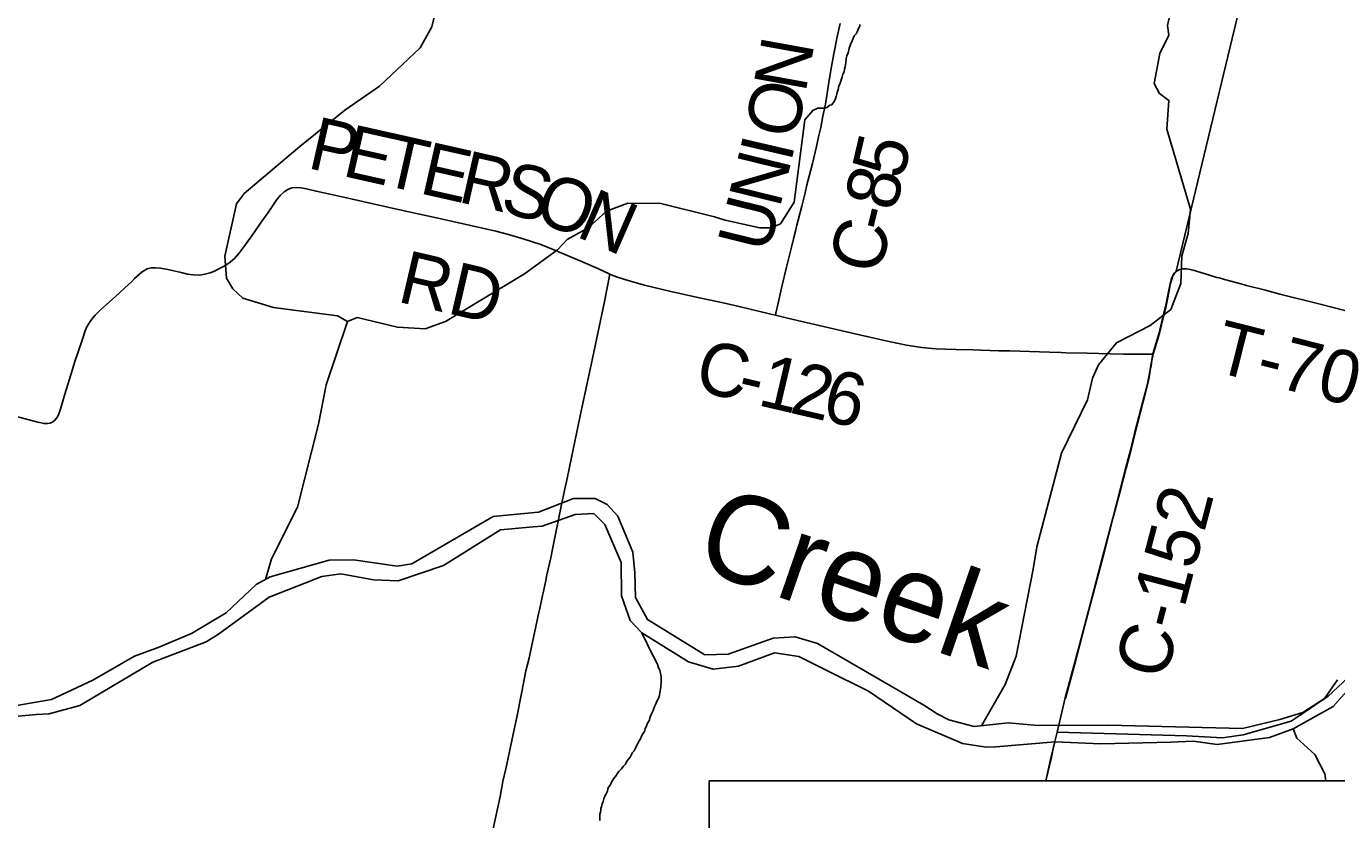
# Model space of a CAD drawing. Extents: x -1.4 to 35.4, y 0 to 22.
# Drawn here: x 12.391 to 13.799, y 14.45 to 15.303 of the extents above; entities that cross this region are included whole.
import ezdxf

# ---------------------------------------------------------------- set-up
doc = ezdxf.new("R2010")
doc.units = 0
for name, color, linetype in [('GM_X_County_Road', 7, 'Continuous'), ('GM_X_County_Road_Text', 7, 'Continuous'), ('GM_X_Major_River', 7, 'Continuous'), ('GM_X_Major_River_Text', 7, 'Continuous'), ('GM_X_Minor_River', 7, 'Continuous'), ('GM_X_Township_Road', 7, 'Continuous'), ('GM_X_Township_Road_Text', 7, 'Continuous'), ('SC_Scratch1', 7, 'Continuous'), ('SH_Data', 7, 'Continuous')]:
    doc.layers.add(name, color=color, linetype=linetype)

msp = doc.modelspace()

# ---------------------------------------------------------------- linework, layer by layer
at = {"layer": 'GM_X_County_Road'}
for points in [[(13.1957, 14.9926), (13.1961, 14.9947), (13.1984, 15.0054), (13.2027, 15.0249), (13.2075, 15.0442), (13.2132, 15.0671), (13.2154, 15.0762), (13.217, 15.0828), (13.2187, 15.0894), (13.22, 15.0948), (13.2238, 15.1099), (13.2274, 15.124), (13.2294, 15.1329), (13.2316, 15.1419), (13.2352, 15.1557), (13.2397, 15.1739), (13.2419, 15.1844), (13.2442, 15.1943), (13.2465, 15.2064), (13.2492, 15.2195), (13.2534, 15.2452), (13.2558, 15.2599), (13.2581, 15.2737), (13.2618, 15.2919), (13.265, 15.3063)], [(12.892, 14.4391), (12.8963, 14.4591), (12.8998, 14.4755), (12.9028, 14.4914), (12.9059, 14.5053), (12.9084, 14.5169), (12.9139, 14.5424), (12.9172, 14.5588), (12.9229, 14.5879), (12.9275, 14.6103), (12.9308, 14.6242), (12.9339, 14.6381), (12.9379, 14.6563), (12.9397, 14.6648), (12.9414, 14.6733), (12.9423, 14.6775), (12.9454, 14.6914), (12.946, 14.6944), (12.9467, 14.6974), (12.9488, 14.7076), (12.9501, 14.7137), (12.9541, 14.7319), (12.9559, 14.7411), (12.9655, 14.7873), (12.9694, 14.8061), (12.9717, 14.8171), (12.9765, 14.8396), (12.9873, 14.8913), (12.9969, 14.9362), (12.9989, 14.946), (13.006, 14.98), (13.0115, 15.0056), (13.0177, 15.0366)], [(13.0177, 15.0366), (13.0207, 15.0354), (13.026, 15.0335), (13.0385, 15.0294), (13.0547, 15.0249), (13.0831, 15.0182), (13.1171, 15.0106), (13.1395, 15.0058), (13.1564, 15.0019), (13.1697, 14.9987), (13.1893, 14.9942), (13.1957, 14.9926)], [(13.1957, 14.9926), (13.2085, 14.9895), (13.2532, 14.9792), (13.2859, 14.9717), (13.3192, 14.964), (13.3363, 14.9606), (13.3529, 14.958), (13.364, 14.9569), (13.3683, 14.9566), (13.3783, 14.956), (13.3894, 14.9557), (13.408, 14.9553), (13.4161, 14.9551), (13.4354, 14.9545), (13.4472, 14.9543), (13.49, 14.9528), (13.5024, 14.9524), (13.5074, 14.9523), (13.5303, 14.9519), (13.5551, 14.9512), (13.5694, 14.9509), (13.6013, 14.9506)], [(13.5071, 14.5808), (13.5172, 14.6178), (13.5281, 14.6594), (13.5486, 14.7375), (13.5582, 14.7741), (13.5667, 14.806), (13.5724, 14.8283), (13.5772, 14.847), (13.5821, 14.8663), (13.5906, 14.8994), (13.5953, 14.9179), (13.5963, 14.9225), (13.5969, 14.9255), (13.5974, 14.9281), (13.5983, 14.9336), (13.5991, 14.9382), (13.6001, 14.9439), (13.6013, 14.9506)], [(13.4862, 14.4922), (13.492, 14.5178), (13.4941, 14.5265), (13.4958, 14.534)]]:
    msp.add_lwpolyline(points, dxfattribs=at)
at = {"layer": 'GM_X_Major_River'}
for points in [[(13.7994, 14.6009), (13.7856, 14.5807), (13.7621, 14.5656), (13.7376, 14.5582), (13.6974, 14.5485), (13.5534, 14.5522), (13.4778, 14.5517), (13.4455, 14.5547), (13.409, 14.5506), (13.3818, 14.5577), (13.3694, 14.5644), (13.3551, 14.5735), (13.2407, 14.64), (13.2169, 14.647), (13.193, 14.6457), (13.1447, 14.6282), (13.1196, 14.6276), (13.0581, 14.6655), (13.0453, 14.6894), (13.0444, 14.7156), (13.0423, 14.7381), (13.0261, 14.7765), (13.0149, 14.7893), (13.0018, 14.7957), (12.9786, 14.7958), (12.941, 14.7811), (12.9029, 14.7774), (12.8922, 14.7762), (12.8048, 14.7253), (12.7891, 14.723), (12.7422, 14.7298), (12.7159, 14.7293), (12.6528, 14.7114), (12.6378, 14.7034), (12.6055, 14.6729), (12.5681, 14.6506), (12.5324, 14.6355), (12.5071, 14.6262), (12.462, 14.6003), (12.4178, 14.5796), (12.3572, 14.5692)], [(13.8445, 14.628), (13.7949, 14.5721), (13.7518, 14.548), (13.7265, 14.5387), (13.67, 14.5313), (13.6443, 14.5349), (13.6203, 14.5339), (13.545, 14.5319), (13.496, 14.5341), (13.4324, 14.5288), (13.4221, 14.5283), (13.3964, 14.5323), (13.3471, 14.5535), (13.2954, 14.5886), (13.2492, 14.6117), (13.2206, 14.626), (13.1945, 14.6297), (13.1558, 14.6154), (13.1287, 14.6122), (13.1023, 14.62), (13.0521, 14.6512), (13.0394, 14.6644), (13.0302, 14.6912), (13.0299, 14.727), (13.0122, 14.7677), (13.0003, 14.7794), (12.9805, 14.7783), (12.9448, 14.7658), (12.9353, 14.7653), (12.9003, 14.7619), (12.8389, 14.7238), (12.7903, 14.7071), (12.7637, 14.7084), (12.7285, 14.7146), (12.7083, 14.712), (12.6515, 14.6897), (12.597, 14.65), (12.5839, 14.6415), (12.5267, 14.6197), (12.4481, 14.5732), (12.4152, 14.5641), (12.4011, 14.5637), (12.371, 14.5605)]]:
    msp.add_lwpolyline(points, dxfattribs=at)
at = {"layer": 'GM_X_Minor_River'}
for points in [[(13.1156, 15.6524), (13.0916, 15.6472), (13.0709, 15.6347), (13.065, 15.6241), (13.0648, 15.59), (13.0616, 15.5783), (13.0415, 15.5573), (13.0288, 15.5241), (13.0185, 15.5042), (13.01, 15.4937), (12.9989, 15.4863), (12.9922, 15.475), (12.9588, 15.4543), (12.9446, 15.4208), (12.9097, 15.3785), (12.8966, 15.3703), (12.8622, 15.3565), (12.8403, 15.3383), (12.8321, 15.3259), (12.8264, 15.3024), (12.8138, 15.2799), (12.7702, 15.2389), (12.733, 15.2129)], [(13.6162, 15.1924), (13.6182, 15.2235), (13.6081, 15.2309), (13.6026, 15.2416), (13.6084, 15.2738), (13.6183, 15.2937), (13.6166, 15.304), (13.6243, 15.3377), (13.6308, 15.3596), (13.6422, 15.3837), (13.6716, 15.4151), (13.6818, 15.4358), (13.6932, 15.4724)], [(13.2272, 15.2027), (13.2359, 15.2131), (13.2389, 15.2142), (13.2408, 15.215), (13.2439, 15.215), (13.2484, 15.2153), (13.2507, 15.216), (13.2541, 15.2183), (13.256, 15.2186), (13.2572, 15.2205), (13.2591, 15.2228), (13.2599, 15.2254), (13.2607, 15.2277), (13.2614, 15.2304), (13.2622, 15.233), (13.263, 15.2353), (13.2638, 15.2391), (13.2649, 15.241), (13.2657, 15.244), (13.2665, 15.2466), (13.2673, 15.2489), (13.2681, 15.2515), (13.2692, 15.2542), (13.2696, 15.2569), (13.2704, 15.2595), (13.2708, 15.2622), (13.2712, 15.264), (13.2716, 15.2686), (13.2724, 15.2712), (13.2735, 15.2747), (13.2747, 15.2796), (13.2763, 15.2837), (13.2778, 15.2875), (13.2801, 15.2928), (13.2824, 15.2951), (13.2832, 15.2973), (13.2847, 15.3007), (13.2859, 15.3026), (13.2867, 15.3049)], [(12.7358, 14.9857), (12.7249, 14.992), (12.6564, 15.0009), (12.6232, 15.0111), (12.6124, 15.0209), (12.6058, 15.0324), (12.6041, 15.056), (12.6166, 15.1123), (12.6249, 15.1235), (12.6847, 15.1738), (12.733, 15.2129)], [(12.6476, 14.7086), (12.654, 14.7308), (12.6821, 14.7864), (12.7045, 14.8755), (12.713, 14.9179), (12.7357, 14.9857), (12.7461, 14.99), (12.7895, 14.9799), (12.8191, 14.978), (12.8412, 14.9859), (12.9258, 15.0371), (12.9613, 15.0628), (12.9718, 15.074), (12.9944, 15.0864), (13.0142, 15.1045), (13.0371, 15.1131), (13.0724, 15.1126), (13.1301, 15.0984), (13.1414, 15.0947), (13.1788, 15.0866), (13.1906, 15.0867), (13.2009, 15.091), (13.2155, 15.1142), (13.2272, 15.2027)], [(13.4171, 14.5515), (13.4423, 14.5957), (13.454, 14.6262), (13.4723, 14.7196), (13.4762, 14.7438), (13.503, 14.8442), (13.5308, 14.9017), (13.5362, 14.9251), (13.5426, 14.9394), (13.5621, 14.9629), (13.5982, 14.9814), (13.6202, 14.9988), (13.631, 15.0266), (13.632, 15.0566), (13.639, 15.0804), (13.6414, 15.1065), (13.6162, 15.1924)], [(13.0521, 14.6512), (13.0633, 14.6275), (13.0655, 14.624), (13.0666, 14.6217), (13.0689, 14.6175), (13.07, 14.6137), (13.0715, 14.6111), (13.0726, 14.6042), (13.0726, 14.6008), (13.0729, 14.597), (13.0725, 14.5947), (13.0725, 14.5928), (13.0717, 14.589), (13.0713, 14.5864), (13.0706, 14.5829), (13.0698, 14.5807), (13.0682, 14.578), (13.0675, 14.5757), (13.0659, 14.5727), (13.0648, 14.5701), (13.064, 14.5678), (13.0628, 14.5651), (13.0613, 14.5617), (13.0605, 14.5598), (13.0601, 14.5575), (13.0582, 14.5541), (13.0574, 14.5522), (13.0555, 14.5481), (13.0547, 14.5454), (13.0532, 14.5428), (13.0516, 14.5401), (13.0505, 14.5375), (13.0493, 14.5352), (13.0478, 14.5325), (13.0459, 14.5291), (13.0447, 14.5265), (13.0436, 14.5246), (13.042, 14.5227), (13.0409, 14.5204), (13.0393, 14.5178), (13.0374, 14.5151), (13.0355, 14.5125), (13.0343, 14.5102), (13.032, 14.5076), (13.0301, 14.5053), (13.0274, 14.5023), (13.0259, 14.5004), (13.0247, 14.4985), (13.0217, 14.4943), (13.0198, 14.4917), (13.019, 14.4898), (13.0178, 14.4875), (13.0163, 14.4853), (13.0155, 14.4834), (13.0151, 14.4811), (13.0136, 14.4784), (13.0124, 14.4758), (13.0113, 14.4728), (13.0105, 14.4701), (13.0093, 14.4675), (13.0085, 14.4644), (13.0078, 14.4625), (13.0078, 14.4606), (13.0077, 14.4587), (13.007, 14.4564), (13.007, 14.4542), (13.0069, 14.4523), (13.0069, 14.4496)], [(13.7518, 14.548), (13.7556, 14.5382), (13.775, 14.5207), (13.7859, 14.4999), (13.7868, 14.4922)]]:
    msp.add_lwpolyline(points, dxfattribs=at)
at = {"layer": 'GM_X_Township_Road'}
for points in [[(12.3591, 14.8893), (12.391, 14.8809), (12.403, 14.8778), (12.4098, 14.8762), (12.4131, 14.8761), (12.4163, 14.8767), (12.4193, 14.8782), (12.4214, 14.8798), (12.4235, 14.8823), (12.4254, 14.8857), (12.4271, 14.8905), (12.432, 14.9077), (12.4353, 14.9183), (12.4398, 14.9333), (12.4413, 14.9381), (12.4433, 14.9439), (12.446, 14.9522), (12.451, 14.9669), (12.454, 14.9757), (12.4562, 14.9807), (12.4575, 14.9831), (12.4593, 14.986), (12.4621, 14.9899), (12.4645, 14.9928), (12.4699, 14.9981), (12.4833, 15.01), (12.4903, 15.0163), (12.4967, 15.0219), (12.5036, 15.0286), (12.5071, 15.032), (12.5098, 15.0347), (12.5153, 15.0394), (12.5204, 15.0423), (12.525, 15.0434), (12.5292, 15.0436), (12.5347, 15.0432), (12.5444, 15.0414), (12.5571, 15.0385), (12.5638, 15.0369), (12.57, 15.0359), (12.577, 15.0356), (12.5826, 15.0366), (12.5881, 15.0382), (12.5927, 15.04), (12.5962, 15.0416), (12.6046, 15.0459), (12.6102, 15.05), (12.6145, 15.0537), (12.619, 15.059), (12.6243, 15.066), (12.6337, 15.0791), (12.6447, 15.095), (12.6505, 15.103), (12.6599, 15.1169), (12.6637, 15.1217), (12.6676, 15.1254), (12.6716, 15.1279), (12.6761, 15.1295), (12.6808, 15.1298), (12.6857, 15.1295), (12.6917, 15.1283), (12.702, 15.1259), (12.7152, 15.1229), (12.741, 15.1172), (12.7616, 15.1128), (12.7967, 15.1048), (12.8313, 15.0972), (12.8665, 15.0894), (12.895, 15.0829), (12.9088, 15.0793), (12.9254, 15.0744), (12.9425, 15.0689), (12.9524, 15.0652), (12.989, 15.0498), (13.0049, 15.0427), (13.0177, 15.0366)], [(13.6013, 14.9506), (13.6081, 14.9733), (13.6129, 14.9927), (13.6148, 15.0009), (13.6164, 15.0082), (13.6189, 15.021), (13.6198, 15.0256), (13.6204, 15.0283), (13.6209, 15.0303), (13.6216, 15.0325), (13.6223, 15.0341), (13.6229, 15.0353), (13.6236, 15.0363), (13.6243, 15.0374), (13.6252, 15.0384), (13.6262, 15.0394)], [(13.6262, 15.0394), (13.6269, 15.04), (13.6279, 15.0407), (13.6296, 15.0416), (13.6314, 15.0421), (13.6327, 15.0424), (13.6338, 15.0425), (13.6351, 15.0426), (13.6363, 15.0425), (13.6377, 15.0424), (13.6395, 15.0421), (13.6442, 15.0409), (13.6561, 15.0374), (13.6698, 15.0333), (13.6722, 15.0327), (13.6733, 15.0323), (13.6757, 15.0316), (13.6781, 15.0309), (13.6901, 15.0277), (13.6955, 15.0263), (13.7015, 15.0247), (13.7219, 15.0194), (13.7375, 15.0152), (13.7531, 15.0114), (13.7622, 15.0092), (13.7821, 15.0043), (13.8157, 14.9957)]]:
    msp.add_lwpolyline(points, dxfattribs=at)
at = {"layer": 'SC_Scratch1'}
for points in [[(13.4859, 14.4922), (13.4918, 14.5183), (13.4938, 14.5271), (13.4956, 14.5345), (13.4981, 14.5444), (13.5068, 14.5813), (13.517, 14.6184), (13.5279, 14.6599), (13.5484, 14.738), (13.558, 14.7746), (13.5664, 14.8066), (13.5721, 14.8288), (13.577, 14.8475), (13.5818, 14.8668), (13.5903, 14.8999), (13.5951, 14.9184), (13.5961, 14.923), (13.5967, 14.926), (13.5971, 14.9287), (13.5981, 14.9341), (13.5988, 14.9387), (13.5999, 14.9444), (13.6011, 14.9511), (13.6078, 14.9738), (13.6126, 14.9933), (13.6146, 15.0015), (13.6162, 15.0087), (13.6187, 15.0215), (13.6196, 15.0262), (13.6202, 15.0288), (13.6206, 15.0308), (13.6214, 15.033), (13.6221, 15.0346), (13.6227, 15.0358), (13.6233, 15.0369), (13.6241, 15.0379), (13.6249, 15.039), (13.6259, 15.0399), (13.7209, 15.4347)], [(13.7209, 15.4347), (13.6259, 15.0399), (13.6249, 15.039), (13.6241, 15.0379), (13.6233, 15.0369), (13.6227, 15.0358), (13.6221, 15.0346), (13.6214, 15.033), (13.6206, 15.0308), (13.6202, 15.0288), (13.6196, 15.0262), (13.6187, 15.0215), (13.6162, 15.0087), (13.6146, 15.0015), (13.6126, 14.9933), (13.6078, 14.9738), (13.6011, 14.9511), (13.5999, 14.9444), (13.5988, 14.9387), (13.5981, 14.9341), (13.5971, 14.9287), (13.5967, 14.926), (13.5961, 14.923), (13.5951, 14.9184), (13.5903, 14.8999), (13.5818, 14.8668), (13.577, 14.8475), (13.5721, 14.8288), (13.5664, 14.8066), (13.558, 14.7746), (13.5484, 14.738), (13.5279, 14.6599), (13.517, 14.6184), (13.5068, 14.5813), (13.4981, 14.5444), (13.637, 14.5407), (13.6757, 14.5385), (13.6982, 14.5417), (13.7496, 14.5565), (13.7893, 14.5832), (13.8104, 14.6028)], [(13.8104, 14.6028), (13.7893, 14.5832), (13.7496, 14.5565), (13.6982, 14.5417), (13.6757, 14.5385), (13.637, 14.5407), (13.4981, 14.5444), (13.4956, 14.5345), (13.4938, 14.5271), (13.4918, 14.5183), (13.4859, 14.4922)]]:
    msp.add_lwpolyline(points, dxfattribs=at)
at = {"layer": 'SH_Data'}
msp.add_lwpolyline([(13.1243, 14.4922), (14.3943, 14.4922), (14.3943, 14.3747), (15.1442, 14.7096), (14.3943, 14.2522), (14.3943, 14.1722), (13.1243, 14.1722)], close=True, dxfattribs=at)

# ---------------------------------------------------------------- texts
at = {"layer": 'GM_X_County_Road_Text'}
for s, height, rotation, p in [('N', 0.0568, 79.7032, (13.2278, 15.2306)), ('O', 0.0568, 78.8025, (13.2179, 15.1806)), ('I', 0.0568, 76.8865, (13.2122, 15.1558)), ('5', 0.0568, 76.8408, (13.3324, 15.1372)), ('N', 0.0568, 76.1977, (13.2001, 15.1066)), ('8', 0.0568, 76.4219, (13.3241, 15.1028)), ('U', 0.0568, 76.1316, (13.1881, 15.0579)), ('C', 0.0568, 76.3197, (13.3075, 15.0346)), ('-', 0.0568, 76.3277, (13.3185, 15.08)), ('C', 0.0568, 346.7608, (13.1068, 14.9123)), ('1', 0.0568, 346.8074, (13.175, 14.8963)), ('2', 0.0568, 346.9465, (13.2093, 14.8882)), ('6', 0.0568, 347.4695, (13.2439, 14.8802)), ('-', 0.0568, 346.7797, (13.1523, 14.9016)), ('C-152', 0.05682, 75.2995, (13.6144, 14.5992))]:
    msp.add_text(s, height=height, rotation=rotation, dxfattribs=at).set_placement(p)
at = {"layer": 'GM_X_Major_River_Text'}
msp.add_text('Creek', height=0.09469, rotation=340.9277, dxfattribs=at).set_placement((13.1056, 14.722))
at = {"layer": 'GM_X_Township_Road_Text'}
for s, height, rotation, p in [('P', 0.0568, 347.2903, (12.6913, 15.1511)), ('E', 0.0568, 347.2881, (12.7287, 15.1427)), ('T', 0.0568, 347.2902, (12.7702, 15.1334)), ('E', 0.0568, 347.2881, (12.8116, 15.124)), ('R', 0.0568, 347.1414, (12.853, 15.1147)), ('S', 0.0568, 345.255, (12.898, 15.1044)), ('O', 0.0568, 339.5279, (12.9337, 15.0951)), ('N', 0.0568, 336.4599, (12.9798, 15.0779)), ('RD', 0.05682, 346.8961, (12.7879, 15.0075)), ('T-70', 0.05682, 345.7946, (13.6643, 14.9328))]:
    msp.add_text(s, height=height, rotation=rotation, dxfattribs=at).set_placement(p)

doc.saveas('drawing.dxf')
